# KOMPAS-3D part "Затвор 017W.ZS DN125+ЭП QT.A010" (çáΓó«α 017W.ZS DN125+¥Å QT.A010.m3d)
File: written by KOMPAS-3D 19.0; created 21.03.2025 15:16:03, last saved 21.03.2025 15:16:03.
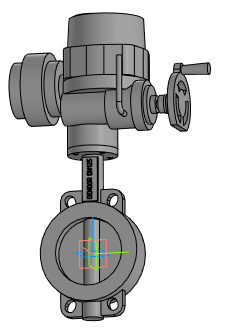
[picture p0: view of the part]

Document properties: Полное имя файла: Затвор 017W.ZS DN125+ЭП QT.A010.a3d

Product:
- Part/product: Затвор 017W.ZS DN125+ЭП QT.A010
    Масса: 45.5295

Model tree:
1. Операция без истории:1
